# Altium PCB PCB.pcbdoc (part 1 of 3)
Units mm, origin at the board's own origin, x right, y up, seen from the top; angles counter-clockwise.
Board outline 65.2 x 64.45 mm, 2 copper layers (Top Layer, Bottom Layer); 194 components, 135 nets, 803 pads, 401 vias.
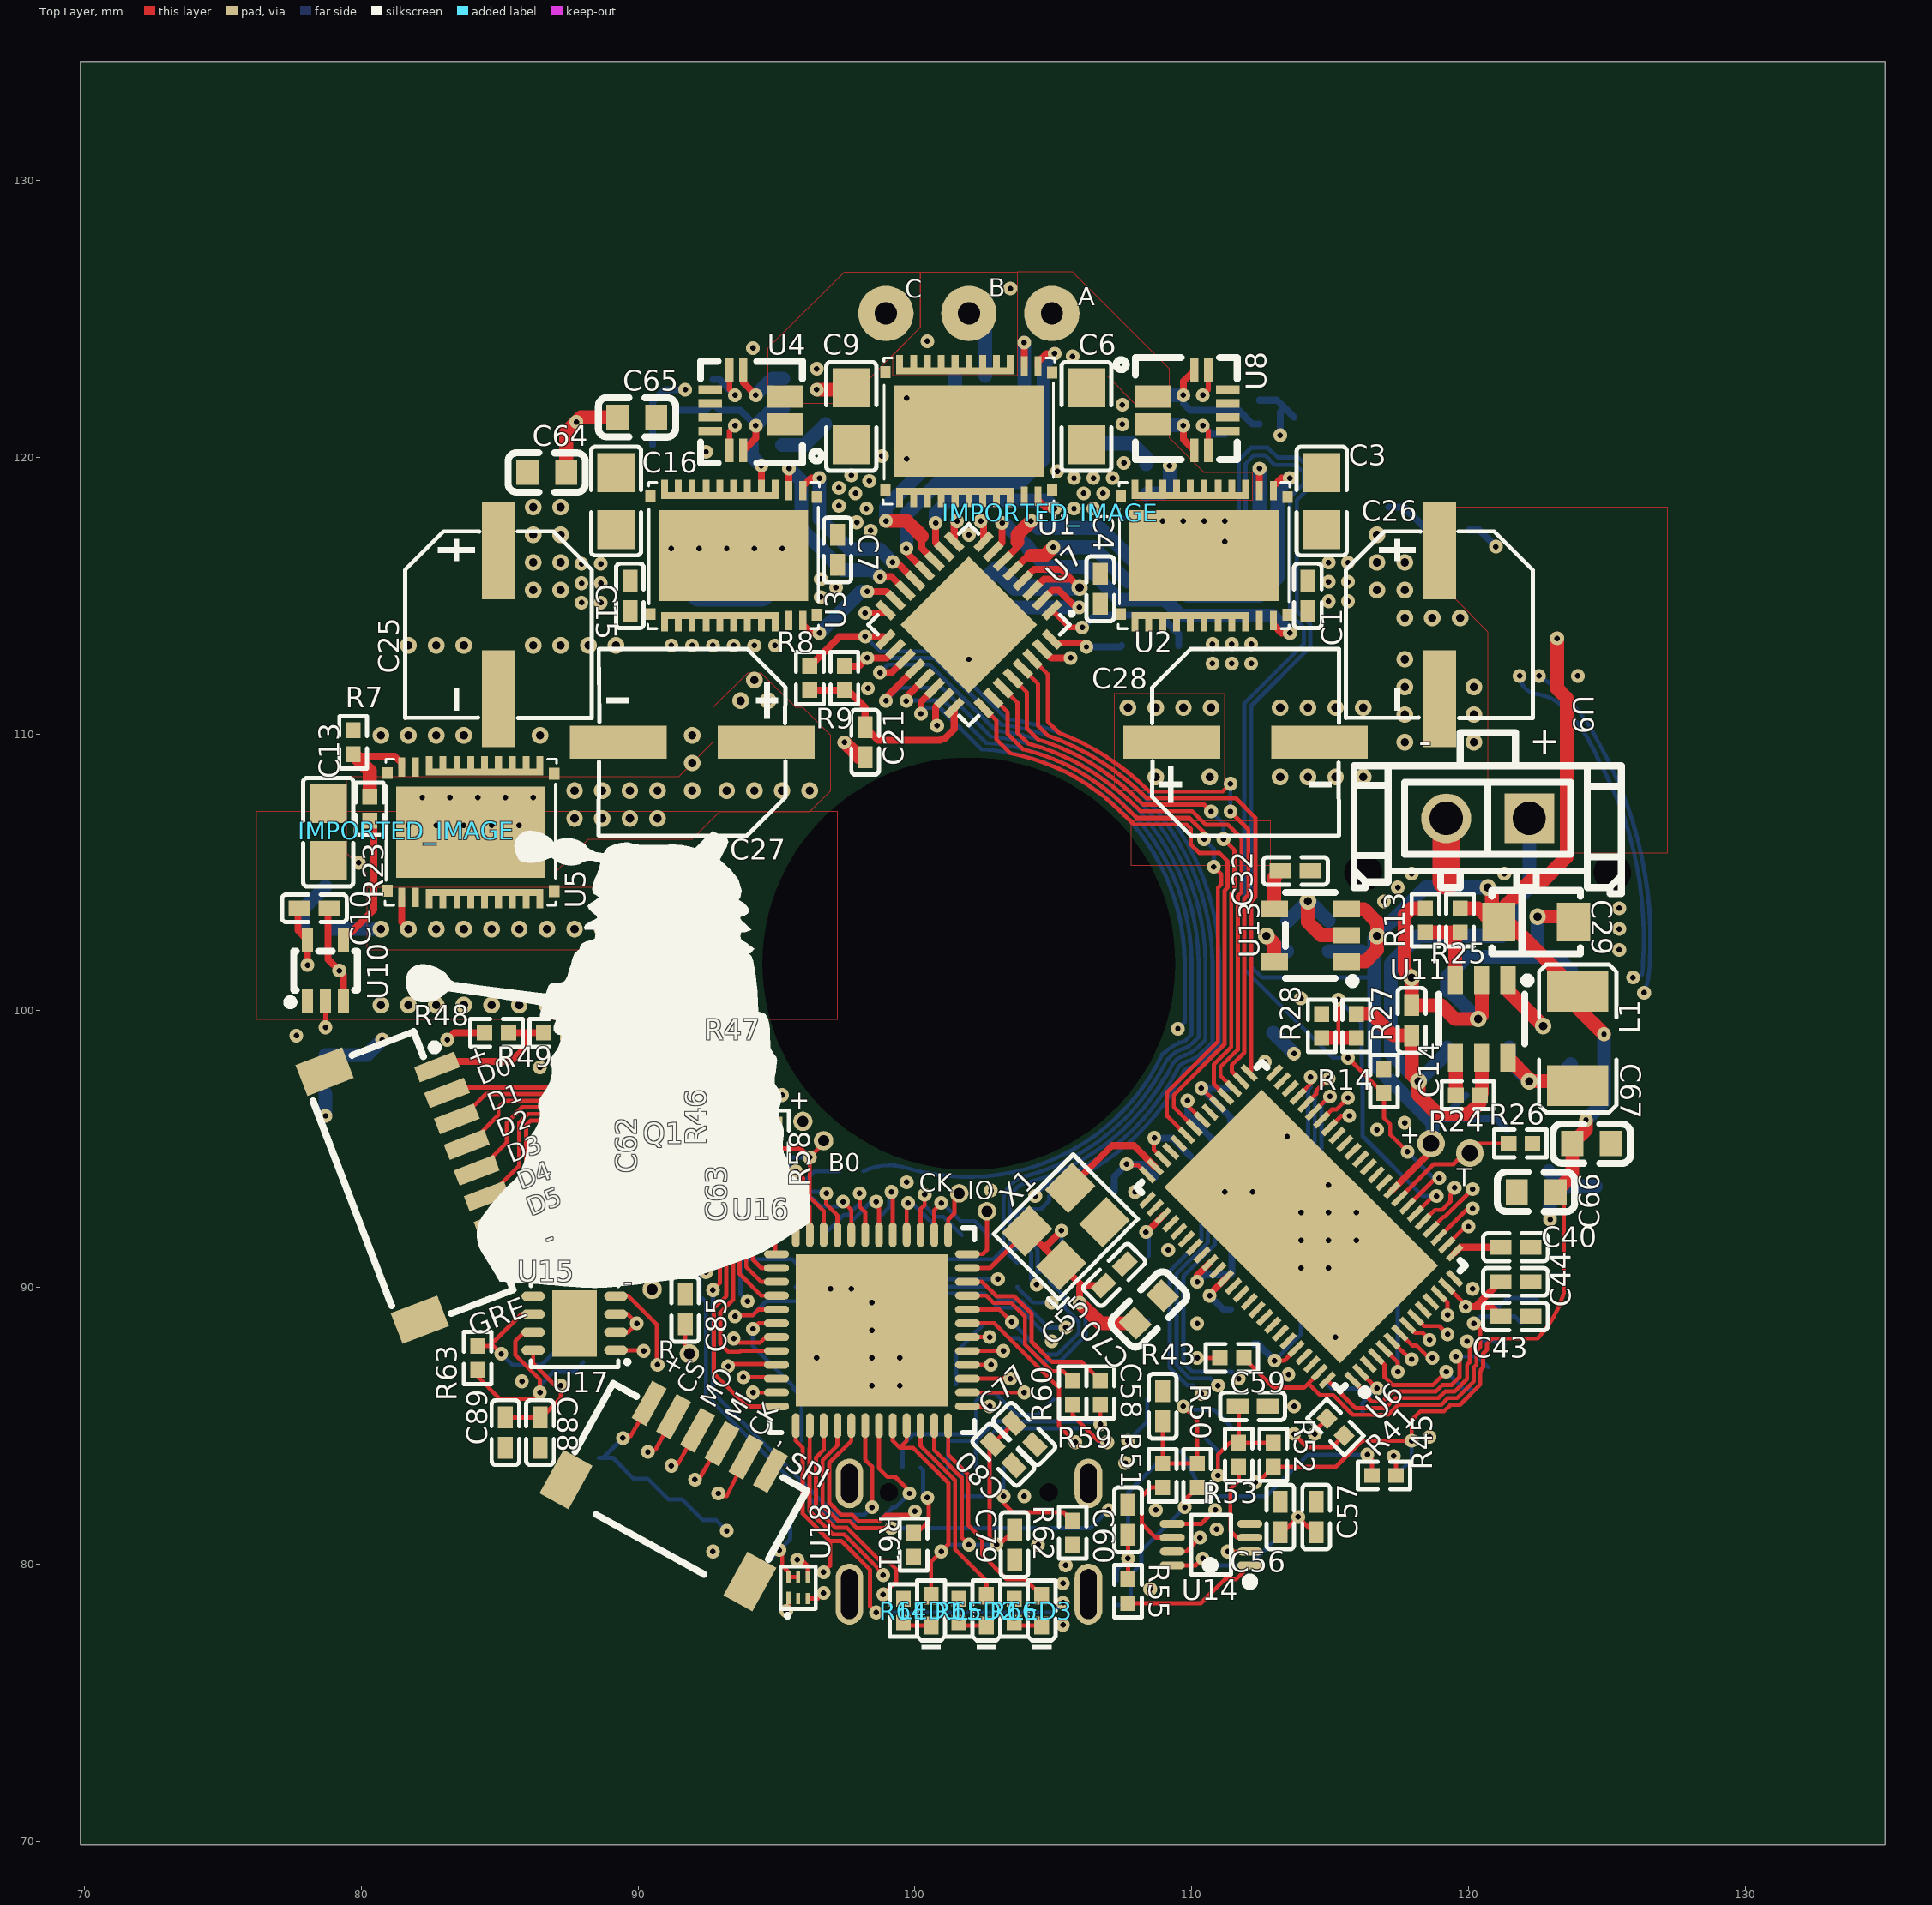
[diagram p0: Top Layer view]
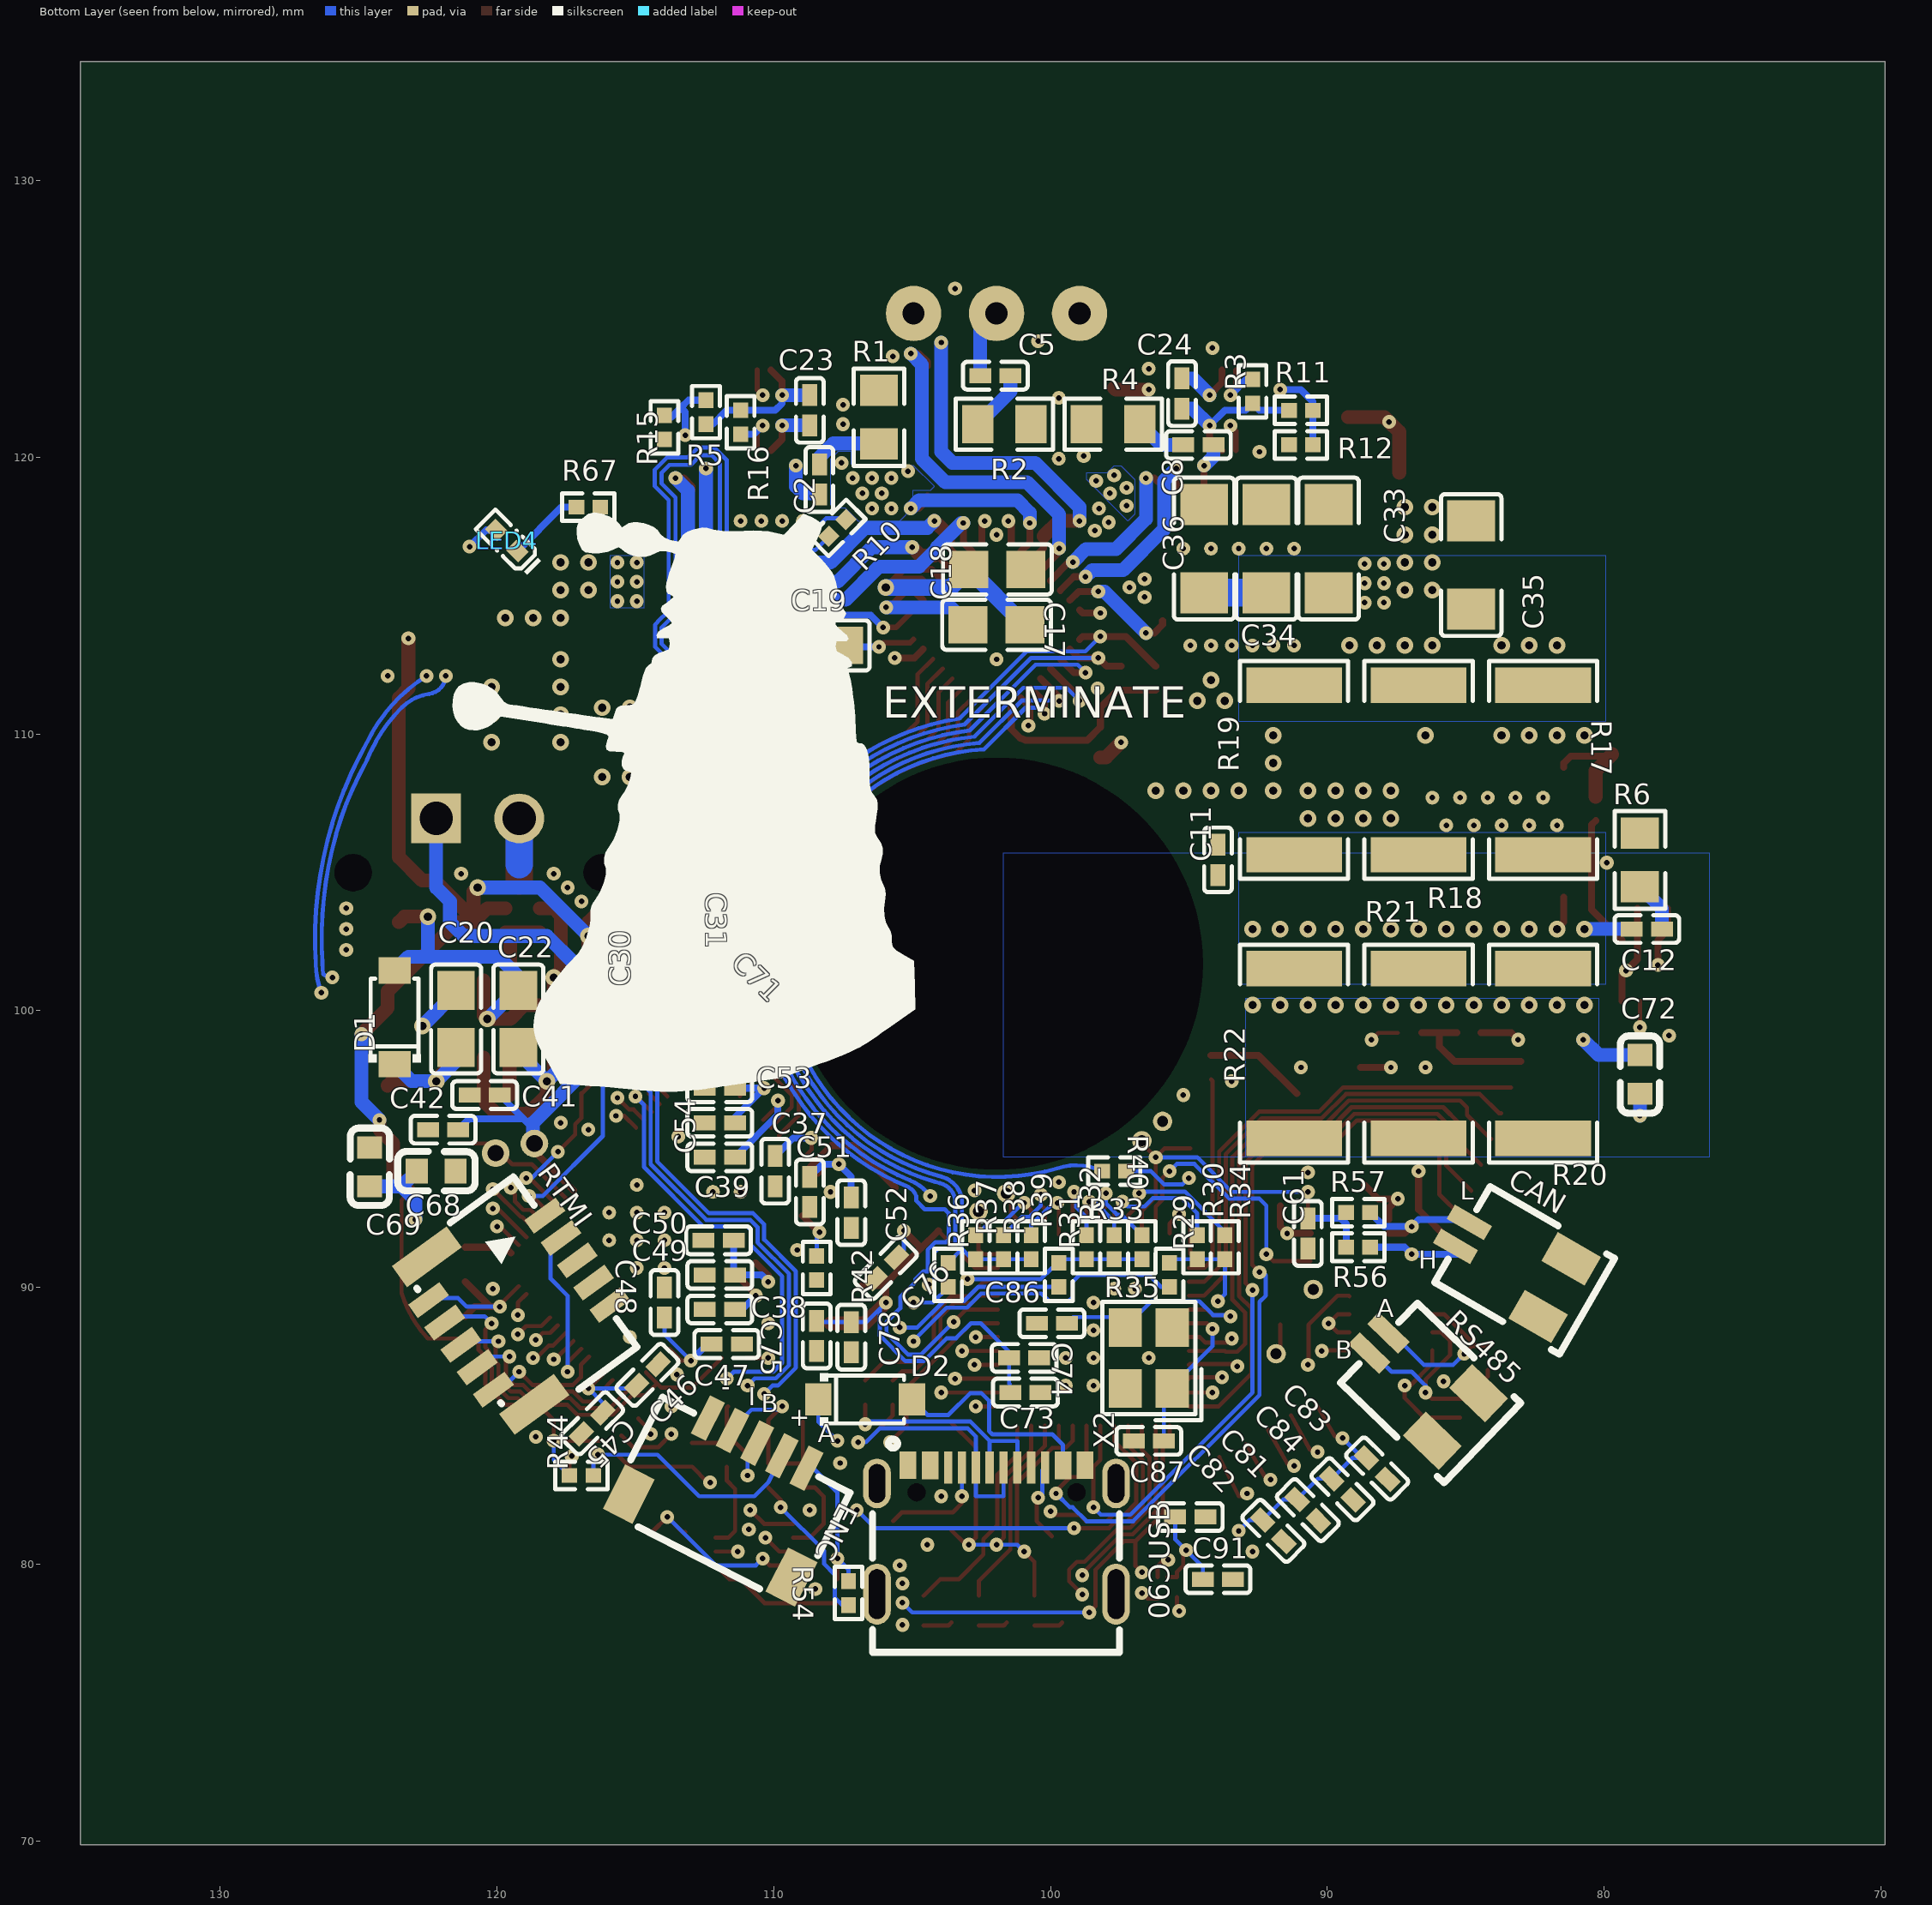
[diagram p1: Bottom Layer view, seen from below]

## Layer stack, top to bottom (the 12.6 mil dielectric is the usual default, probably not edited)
Top Solder: solder mask 0.0102, Solder Resist, Dk 3.5
Top Layer: signal copper 0.0356
Dielectric 1: dielectric 0.32, FR-4, Dk 4.8
Bottom Layer: signal copper 0.0356
Bottom Solder: solder mask 0.0102, Solder Resist, Dk 3.5

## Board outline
135.05,69.85 69.85,69.85 69.85,134.3 135.05,134.3
cut-out: 109.4,101.7 ccw(c101.95,101.7) 94.5,101.7 ccw(c101.95,101.7)
cut-out: 105.165,82.593 ccw(c104.84,82.593) 104.515,82.593 ccw(c104.84,82.593)
cut-out: 99.385,82.593 ccw(c99.06,82.593) 98.735,82.593 ccw(c99.06,82.593)

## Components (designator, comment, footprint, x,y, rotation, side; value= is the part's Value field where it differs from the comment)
C1 "CC0402KRX7R0BB103" C0402 114.2,114.995 r270 top
C2 "GRM155R72A472KA01D" C0402 108.35,119.2 r270 bottom
C3 "CL21B104KCFNNNE" C0805 114.7,118.42 r90 top
C4 "CC0402KRX7R0BB103" C0402 106.7,115.245 r270 top
C5 "GRM155R72A472KA01D" C0402 101.995,122.95 r0 bottom
C6 "CL21B104KCFNNNE" C0805 106.2,121.48 r90 top
C7 "CC0402KRX7R0BB103" C0402 97.2,116.655 r270 top
C8 "GRM155R72A472KA01D" C0402 94.655,120.45 r180 bottom
C9 "CL21B104KCFNNNE" C0805 97.7,121.48 r90 top
C10 "CC0402KRX7R7BB104" C0402 78.3,103.7 r0 top
C11 "CC0402KRX7R0BB103" C0402 93.95,105.45 r90 bottom
C12 "GRM155R72A472KA01D" C0402 78.45,102.95 r0 bottom
C13 "CL21B104KCFNNNE" C0805 78.8,106.45 r90 top
C14 "CC0402KRX7R0BB103" C0402 117.95,99.655 r90 top
C15 "CC0402KRX7R0BB103" C0402 89.7,114.995 r270 top
C16 "CL21B104KCFNNNE" C0805 89.2,118.42 r90 top
C17 "C0805X105K101T" C0805 101.95,113.95 r0 bottom
C18 "CL21B104KCFNNNE" C0805 101.92,115.95 r0 bottom
C19 "C2012X7R2A473KT0L0U" C0805 108.5,113.2 r0 bottom
C20 "CL21B104KCFNNNE" C0805 119.23,99.7 r90 bottom
C21 "CL05A105KA5NQNC" C0402 98.2,109.7 r90 top
C22 "CL21B104KCFNNNE" C0805 121.48,99.7 r270 bottom
C23 "CC0402KRX7R7BB104" C0402 108.7,121.7 r90 bottom
C24 "CC0402KRX7R7BB104" C0402 95.25,122.305 r270 bottom
C25 "VKMC1201J680MV" CAP-SMD_BD6.3-L6.6-W6.6-LS7.6-FD 84.95,113.95 r270 top
C26 "VKMC1201J680MV" CAP-SMD_BD6.3-L6.6-W6.6-LS7.6-FD 118.95,113.95 r270 top
C27 "VKMC1201J680MV" CAP-SMD_BD6.3-L6.6-W6.6-LS7.6-FD 91.95,109.7 r180 top
C28 "VKMC1201J680MV" CAP-SMD_BD6.3-L6.6-W6.6-LS7.6-FD 111.95,109.7 r0 top
C29 "TLJA107M010R1400" CAP-SMD_L3.2-W1.6 122.45,103.2 r0 top
C30 "CL05A106MP5NUNC" C0402 114.95,102.7 r270 bottom
C31 "GRM155R60J226ME11D" C0402 113.45,102.7 r270 bottom
C32 "CL05B103KB5NNNC" C0402 113.75,105.05 r180 top
C33 "GRM31CC72A475KE11L" C1206 89.95,116.7 r90 bottom
C34 "GRM31CC72A475KE11L" C1206 92.2,116.7 r90 bottom
C35 "GRM31CC72A475KE11L" C1206 84.8,116.107 r90 bottom
C36 "GRM31CC72A475KE11L" C1206 94.45,116.7 r90 bottom
C37 "CC0402KRX7R7BB104" C0402 109.95,94.2 r90 bottom
C38 "CC0402KRX7R7BB104" C0402 111.95,89.2 r180 bottom
C39 "CC0402KRX7R7BB104" C0402 111.95,94.7 r0 bottom
C40 "CC0402KRX7R7BB104" C0402 121.7,91.45 r0 top
C41 "CC0402KRX7R7BB104" C0402 120.45,96.95 r0 bottom
C42 "CL05A106MP5NUNC" C0402 121.95,95.7 r180 bottom
C43 "CC0402KRX7R7BB104" C0402 121.7,88.95 r0 top
C44 "CL05A106MP5NUNC" C0402 121.7,90.2 r180 top
C45 "CC0402KRX7R7BB104" C0402 116.565,85.085 r315 bottom
C46 "CL05A106MP5NUNC" C0402 114.565,86.835 r315 bottom
C47 "CC0402KRX7R7BB104" C0402 111.7,87.95 r180 bottom
C48 "CL05A106MP5NUNC" C0402 113.95,89.45 r270 bottom
C49 "CC0402KRX7R7BB104" C0402 111.95,90.45 r0 bottom
C50 "CL05A106MP5NUNC" C0402 111.995,91.7 r180 bottom
C51 "CC0402KRX7R7BB104" C0402 108.7,93.45 r270 bottom
C52 "CL05A106MP5NUNC" C0402 107.2,92.7 r90 bottom
C53 "CC0402KRX7R7BB104" C0402 111.95,97.2 r0 bottom
C54 "CL05A106MP5NUNC" C0402 111.95,95.95 r180 bottom
C55 "CC0402KRX7R7BB104" C0402 107.2,90.45 r225 top
C56 "CC0402KRX7R7BB104" C0402 113.2,81.7 r90 top
C57 "CL05A106MP5NUNC" C0402 114.5,81.7 r270 top
C58 "CC0402JRNPO9BN101" C0402 108.95,85.7 r270 top
C59 "CC0402JRNPO9BN101" C0402 112.2,85.7 r180 top
C60 "CC0402JRNPO9BN101" C0402 107.7,81.595 r270 top
C61 "0402B472K500CT" C0402 90.7,91.95 r270 bottom
C62 "CC0402KRX7R7BB104" C0402 89.2,93.7 r0 top
C63 "CC0402KRX7R7BB104" C0402 91.7,93.495 r90 top
C64 "CL10A226MP8NUNE" C0603 86.7,119.45 r0 top
C65 "CL10A226MP8NUNE" C0603 89.95,121.45 r180 top
C66 "CL10A226MP8NUNE" C0603 122.45,93.45 r0 top
C67 "CL10A226MP8NUNE" C0603 124.45,95.2 r180 top
C68 "CL10A226MP8NUNE" C0603 122.2,94.2 r0 bottom
C69 "CL10A226MP8NUNE" C0603 124.6,94.35 r270 bottom
C70 "CL10A226MP8NUNE" C0603 108.45,89.2 r225 top
C71 "CL10A226MP8NUNE" C0603 112.45,99.7 r315 bottom
C72 "CL10A226MP8NUNE" C0603 78.7,97.7 r90 bottom
C73 "CC0402KRX7R7BB104" C0402 100.905,86.2 r180 bottom
C74 "CL05A106MP5NUNC" C0402 100.95,87.45 r0 bottom
C75 "CC0402KRX7R7BB104" C0402 108.45,88.245 r270 bottom
C76 "CL05A106MP5NUNC" C0402 105.95,90.7 r135 bottom
C77 "CC0402KRX7R7BB104" C0402 103.95,84.7 r315 top
C78 "CL05A106MP5NUNC" C0402 107.2,88.2 r90 bottom
C79 "CC0402KRX7R7BB104" C0402 103.6,80.7 r270 top
C80 "CL05A106MP5NUNC" C0402 103.2,83.95 r135 top
C81 "CC0402KRX7R7BB104" C0402 90.7,81.95 r225 bottom
C82 "CL05A106MP5NUNC" C0402 91.95,81.2 r45 bottom
C83 "CC0402KRX7R7BB104" C0402 88.2,83.45 r225 bottom
C84 "CL05A106MP5NUNC" C0402 89.45,82.7 r45 bottom
C85 "CC0402KRX7R7BB104" C0402 91.7,89.2 r90 top
C86 "0402CG150J500NT" C0402 99.95,88.7 r180 bottom
C87 "0402CG150J500NT" C0402 96.45,84.45 r180 bottom
C88 "CC0402KRX7R7BB104" C0402 86.45,84.75 r270 top
C89 "CL05A106MP5NUNC" C0402 85.2,84.75 r90 top
C90 "CC0402KRX7R7BB104" C0402 93.95,79.45 r180 bottom
C91 "CL05A106MP5NUNC" C0402 94.95,81.7 r0 bottom
CAN "A1002WR-S-2P" CONN-SMD_A1002WR-S-2P 83.45,90.95 r120 bottom
D1 "DSK16" SOD-123_L2.8-W1.8-LS3.7-RD 123.7,99.758 r90 bottom
D2 "DSK16" SOD-123_L2.8-W1.8-LS3.7-RD 106.7,85.95 r180 bottom
ENC "A1002WR-S-5P" CONN-SMD_A1002WR-S-5P 111.45,82.7 r207 bottom
GRE "A1002WR-S-8P" CONN-SMD_A1002WR-S-8P 82.19,94.005 r291 top
IMPORTED_IMAGE "IMPORTED_IMAGE" IMPORTED_IMAGE 81.613,106.513 r0 top
IMPORTED_IMAGE "IMPORTED_IMAGE" IMPORTED_IMAGE 104.894,118.001 r0 top
L1 "CBC3225T220KR" L1210 123.95,98.997 r90 top
LED1 "MHT136UBCT" LED0402-RD_BLUE 100.584,78.316 r90 top
LED2 "MHT136UBCT" LED0402-RD_BLUE 102.584,78.316 r90 top
LED3 "MHT136UBCT" LED0402-RD_BLUE 104.584,78.316 r90 top
LED4 "MHT136CSCT" LED0402-RD_ORANGE 119.646,116.992 r45 bottom
Q1 "AP2302B" SOT-23_L2.9-W1.3-P1.90-LS2.4-BR 89.95,97.95 r0 top
R1 "0805W8F220KT5E" R0805 106.2,121.45 r270 bottom
R2 "0805W8F220KT5E" R0805 101.666,121.2 r0 bottom
R3 "0402WGF1002TCE" R0402 92.7,122.383 r270 bottom
R4 "0805W8F220KT5E" R0805 97.734,121.2 r180 bottom
R5 "0402WGF1002TCE" R0402 111.2,121.267 r90 bottom
R6 "0805W8F220KT5E" R0805 78.7,105.45 r270 bottom
R7 "0402WGF1002TCE" R0402 79.7,109.7 r270 top
R8 "0402WGF1002TCE" R0402 96.2,112.017 r270 top
R9 "0402WGF1002TCE" R0402 97.45,112.017 r270 top
R10 "NCP15XH103F03RC" R0402 107.7,117.45 r135 bottom
R11 "AR02BTC2001" R0402 90.95,121.7 r0 bottom
R12 "AR02BTC2001" R0402 90.95,120.45 r180 bottom
R13 "0402WGF1002TCE" R0402 118.45,103.267 r270 top
R14 "0402WGF1002TCE" R0402 116.95,97.45 r270 top
R15 "AR02BTC2001" R0402 113.95,121.083 r90 bottom
R16 "AR02BTC2001" R0402 112.45,121.633 r270 bottom
R17 "RC2512JK-7W6R8L" R2512 82.2,108.7 r90 bottom
R18 "RC2512JK-7W6R8L" R2512 86.7,108.7 r270 bottom
R19 "RC2512JK-7W6R8L" R2512 91.2,108.7 r270 bottom
R20 "RC2512JK-7W6R8L" R2512 82.2,98.45 r90 bottom
R21 "RC2512JK-7W6R8L" R2512 86.7,98.45 r90 bottom
R22 "RC2512JK-7W6R8L" R2512 91.2,98.45 r90 bottom
R23 "0402WGJ0561TCE" R0402 80.3,107.3 r90 top
R24 "PTFR0402B100KN9" R0402 119.98,96.95 r0 top
R25 "RTT025492FTH" R0402 119.7,103.267 r90 top
R26 "0402WGF1002TCE" R0402 121.883,95.2 r180 top
R27 "PTFR0402B100KN9" R0402 115.95,99.45 r90 top
R28 "0402WGF1002TCE" R0402 114.7,99.45 r270 top
R29 "RC0402FR-070RL" R0402 95.7,90.45 r270 bottom
R30 "RC0402FR-070RL" R0402 94.7,91.45 r90 bottom
R31 "RC0402FR-070RL" R0402 99.7,90.45 r270 bottom
R32 "RC0402FR-070RL" R0402 98.7,91.45 r90 bottom
R33 "RC0402FR-0718KL" R0402 97.7,91.45 r90 bottom
R34 "0402WGF4532TCE" R0402 93.7,91.45 r90 bottom
R35 "0402WGF7502TCE" R0402 96.7,91.45 r90 bottom
R36 "RC0402FR-070RL" R0402 103.7,90.45 r270 bottom
R37 "RC0402FR-070RL" R0402 102.7,91.45 r90 bottom
R38 "RC0402FR-0718KL" R0402 101.7,91.45 r90 bottom
R39 "0402WGF7502TCE" R0402 100.7,91.45 r90 bottom
R40 "RC0402FR-070RL" R0402 97.7,94.2 r180 bottom
R41 "0402WGF1002TCE" R0402 115.2,84.95 r135 top
R42 "0402WGF1002TCE" R0402 108.45,90.7 r90 bottom
R43 "0402WGF1002TCE" R0402 111.45,87.45 r180 top
R44 "RC0402FR-070RL" R0402 116.95,83.2 r0 bottom
R45 "RC0402FR-070RL" R0402 116.95,83.2 r0 top
R46 "AC0402FR-0710KL" R0402 92.7,97.95 r90 top
R47 "0402WGF2200TCE" R0402 94.2,97.95 r90 top
R48 "RC0402FR-070RL" R0402 84.883,99.2 r180 top
R49 "RC0402FR-070RL" R0402 87.017,99.2 r0 top
R50 "0402WGF1002TCE" R0402 110.2,83.2 r270 top
R51 "AR02BTC2001" R0402 108.95,83.2 r270 top
R52 "0402WGF1002TCE" R0402 112.95,83.95 r270 top
R53 "AR02BTC2001" R0402 111.7,83.95 r90 top
R54 "0402WGF1002TCE" R0402 107.3,78.95 r270 bottom
R55 "AR02BTC2001" R0402 107.7,79.017 r90 top
R56 "0402WGF604JTCE" R0402 88.883,91.45 r0 bottom
R57 "0402WGF604JTCE" R0402 88.883,92.7 r180 bottom
R58 "PTFR0402B100KN9" R0402 94.95,95.45 r90 top
R59 "AC0402FR-0722RL" R0402 106.7,86.2 r90 top
R60 "AC0402FR-0722RL" R0402 105.7,86.2 r90 top
R61 "0402WGF5101TCE" R0402 99.95,80.7 r270 top
R62 "0402WGF5101TCE" R0402 105.7,81.133 r270 top
R63 "RC0402FR-07120RL" R0402 84.2,87.45 r270 top
R64 "AC0402FR-07470RL" R0402 99.584,78.316 r90 top
R65 "AC0402FR-07470RL" R0402 101.584,78.316 r90 top
R66 "AC0402FR-07470RL" R0402 103.584,78.316 r90 top
R67 "0402WGJ0561TCE" R0402 116.7,118.2 r180 bottom
RS485 "A1002WR-S-2P" CONN-SMD_A1002WR-S-2P 86.75,86.651 r134 bottom
RTMI "DF20F-10DP-1H(59)" CONN-SMD_DF20F-10DP-1H-59 119.2,89.45 r234 bottom
SPI "A1002WR-S-6P" CONN-SMD_A1002WR-S-6P 91.65,82.9 r331 top
U1 "CSD88599Q5DCT" SON-22_L5.0-W6.0-P0.50-CSD88599Q5DCT 101.95,120.95 r270 top
U2 "CSD88599Q5DCT" SON-22_L5.0-W6.0-P0.50-CSD88599Q5DCT 110.45,116.45 r270 top
U3 "CSD88599Q5DCT" SON-22_L5.0-W6.0-P0.50-CSD88599Q5DCT 93.45,116.45 r270 top
U4 "ACS711KEXLT-31AB-T" IC-SMD_ACS711KEXLT-15AB-T 93.95,121.7 r180 top
U5 "CSD88599Q5DCT" SON-22_L5.0-W6.0-P0.50-CSD88599Q5DCT 83.95,106.45 r90 top
U6 "TMC4671-LA" QFN-76_L10.5-W6.5-P0.40-TL-EP 113.95,92.2 r135 top
U7 "DRV8320SRTVR" WQFN-32_L5.0-W5.0-P0.50-TL-EP3.5 101.95,113.95 r225 top
U8 "ACS711KEXLT-31AB-T" IC-SMD_ACS711KEXLT-15AB-T 109.95,121.7 r0 top
U9 "436500215" CONN-TH_436500215 120.7,106.95 r0 top
U10 "SN74LVC1G17DCKR" SC-70-5_L2.1-W1.3-P0.65-LS2.1-BR 78.7,101.45 r270 top
U11 "LMR16006XDDCR" SOT-23-6_L2.9-W1.6-P0.95-LS2.8-BR 120.48,99.7 r90 top
U13 "SPX3819M5-L-3-3/TR" SOT-23-5_L3.0-W1.7-P0.95-LS2.8-BR 114.288,102.723 r0 top
U14 "SN74LVC3G17DCUR" VSSOP-8_L2.4-W2.1-P0.50-LS3.2-BL 110.7,80.7 r90 top
U15 "MCP2542FDT-H/MNY" TDFN-8_L3.0-W2.0-P0.50-TL-EP 89.2,91.7 r180 top
U16 "STM32G431CBU6" UFQFPN-48_L7.0-W7.0-P0.50-BL-EP 98.45,88.45 r270 top
U17 "MAX14841EATA+T" TDFN-8_L3.0-W3.0-P0.65-BL-EP 87.7,88.7 r90 top
U18 "SN74LVC1G10DSFR" X2SON-6_L1.0-W1.0-P0.35-TL 95.779,79.146 r90 top
USB "GT-USB-7010B" USB-SMD_GT-USB-7010B 101.95,81.2 r180 bottom
X1 "OT322525MJBA4SL" OSC-SMD_4P-L3.2-W2.5-BL 105.45,92.2 r45 top
X2 "X322524MOB4SI" CRYSTAL-SMD_4P-L3.2-W2.5-BL 96.45,87.45 r90 bottom

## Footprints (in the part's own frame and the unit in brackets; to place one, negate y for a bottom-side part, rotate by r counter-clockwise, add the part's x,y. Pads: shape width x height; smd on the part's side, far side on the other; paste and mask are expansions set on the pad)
C0402 [mm]
  rect 0.79x0.54 smd: 1(-0.545,0) 2(0.545,0)
  silkscreen extent -1.17,-0.5 1.17,0.5
C0603 [mm]
  rect 0.8x0.9 smd: 1(-0.7,0) 2(0.7,0)
  silkscreen extent -1.41,-0.71 1.39,0.72
C0805 [mm]
  rect 1.41x1.35 smd: 1(-1.03,0) 2(1.03,0)
  silkscreen extent -1.96,-0.9 1.96,0.9
C1206 [mm]
  rect 1.485x1.728 smd: 1(-1.593,0) 2(1.593,0)
  silkscreen extent -2.56,-1.09 2.56,1.09
CAP-SMD_BD6.3-L6.6-W6.6-LS7.6-FD [mm]
  rect 3.5x1.2 smd: 1(-2.67,0) 2(2.67,0)
  silkscreen extent -3.38,-3.38 3.38,3.38
CAP-SMD_L3.2-W1.6 [mm]
  rect 1.2x1.4 smd: 1(-1.35,0) 2(1.35,0)
  silkscreen extent -1.6,-1.14 1.6,1.14
CONN-SMD_A1002WR-S-2P [mm]
  rect 0.6x1.55 smd: 1(-0.498,1.924) 2(0.501,1.924)
  rect 1.2x1.8 smd: 3(1.201,-1.924) 4(-1.201,-1.924)
  silkscreen extent -2,-3.27 2,1.92
CONN-SMD_A1002WR-S-5P [mm]
  rect 0.6x1.55 smd: 1(-2,1.876) 2(-1,1.876) 3(0,1.876) 4(1,1.876) 5(2,1.876)
  rect 1.2x1.8 smd: 6(3.3,-1.876) 7(-3.3,-1.876)
  silkscreen extent -3.8,-2.78 3.8,1.8
CONN-SMD_A1002WR-S-6P [mm]
  rect 0.6x1.55 smd: 1(-2.5,1.939) 2(-1.5,1.939) 3(-0.498,1.936) 4(0.501,1.937) 5(1.502,1.937) 6(2.502,1.937)
  rect 1.2x1.8 smd: 7(3.801,-1.939) 8(-3.801,-1.937)
  silkscreen extent -4,-2.51 4,1.93
CONN-SMD_A1002WR-S-8P [mm]
  rect 0.6x1.55 smd: 1(-3.5,1.924) 2(-2.5,1.924) 3(-1.5,1.922) 4(-0.5,1.924) 5(0.5,1.924) 6(1.5,1.924) 7(2.5,1.924) 8(3.5,1.924)
  rect 1.2x1.8 smd: 9(4.8,-1.924) 10(-4.8,-1.924)
  silkscreen extent -5,-2.7 5,2.23
CONN-SMD_DF20F-10DP-1H-59 [mm]
  rect 0.6x1.4 smd: 1(-2,2.6) 2(-2,-2.6) 3(-1,2.6) 4(-1,-2.6) 5(0,2.6) 6(0,-2.6) 7(1,2.6) 8(1,-2.6) 9(2,2.6) 10(2,-2.6)
  rect 0.95x2.45 smd: 11(3.3,-1.725) 12(-3.3,-1.725)
  silkscreen extent -3.8,-2.69 3.8,2.5
CONN-TH_436500215 [mm]
  rect 1.8x1.8 hole 1.2: 1(1.5,0)
  round 1.8 hole 1.2: 2(-1.5,0)
  Multi-Layer board cut-out: -3.825,-1.96 -3.892,-1.667 -4.079,-1.432 -4.35,-1.302 -4.65,-1.302 -4.921,-1.432 -5.108,-1.667 -5.175,-1.96 -5.175,-1.96 -5.108,-2.253 -4.921,-2.488 -4.65,-2.618 -4.35,-2.618 -4.079,-2.488 -3.892,-2.253 -3.825,-1.96
  Multi-Layer board cut-out: 5.175,-1.96 5.108,-1.667 4.921,-1.432 4.65,-1.302 4.35,-1.302 4.079,-1.432 3.892,-1.667 3.825,-1.96 3.825,-1.96 3.892,-2.253 4.079,-2.488 4.35,-2.618 4.65,-2.618 4.921,-2.488 5.108,-2.253 5.175,-1.96
  silkscreen extent -4.83,-2.73 4.83,3.1
CRYSTAL-SMD_4P-L3.2-W2.5-BL [mm]
  rect 1.4x1.2 smd: 1(-1.1,-0.85) 2(1.1,-0.85) 3(1.1,0.85) 4(-1.1,0.85)
  silkscreen extent -2.26,-1.91 2.03,1.68
IC-SMD_ACS711KEXLT-15AB-T [mm]
  rect 1.27x0.8 smd: 1(-1.35,0.5) 2(-1.35,-0.5)
  rect 0.3x0.85 smd: 5(0.15,-1.45) 6(0.65,-1.45) 11(0.65,1.45) 12(0.15,1.45)
  rect 0.85x0.3 smd: 7(1.35,-0.75) 8(1.35,-0.25) 9(1.35,0.25) 10(1.35,0.75)
  silkscreen extent -2.67,-1.78 1.7,1.91
IMPORTED_IMAGE [mm]
  silkscreen extent 0,-16.53 14.59,0
L1210 [mm]
  rect 1.474x2.22 smd: 1(-1.703,0) 2(1.703,0)
  silkscreen extent -2.67,-1.4 2.67,1.4
LED0402-RD_BLUE [mm]
  rect 0.636x0.54 smd: 1(-0.538,0) 2(0.538,0)
  silkscreen extent -1.39,-0.54 1.09,0.54
LED0402-RD_ORANGE [mm]
  rect 0.636x0.54 smd: 1(-0.538,0) 2(0.538,0)
  silkscreen extent -1.39,-0.54 1.09,0.54
OSC-SMD_4P-L3.2-W2.5-BL [mm]
  rect 1.4x1.2 smd: 1(-1.1,-0.875) 2(1.1,-0.875) 3(1.1,0.875) 4(-1.1,0.875)
  silkscreen extent -2.29,-1.9 2.03,1.65
QFN-76_L10.5-W6.5-P0.40-TL-EP [mm]
  rect 0.7x0.205 smd: 1(-5.25,2.6) 2(-5.25,2.2) 3(-5.25,1.8) 4(-5.25,1.4) 5(-5.25,1) 6(-5.25,0.6) 7(-5.25,0.2) 8(-5.25,-0.2) 9(-5.25,-0.6) 10(-5.25,-1) 11(-5.25,-1.4) 12(-5.25,-1.8) 13(-5.25,-2.2) 14(-5.25,-2.6) 39(5.25,-2.6) 40(5.25,-2.2) 41(5.25,-1.8) 42(5.25,-1.4) 43(5.25,-1) 44(5.25,-0.6) 45(5.25,-0.2) 46(5.25,0.2) 47(5.25,0.6) 48(5.25,1) 49(5.25,1.4) 50(5.25,1.8) 51(5.25,2.2) 52(5.25,2.6)
  rect 0.205x0.7 smd: 15(-4.6,-3.25) 16(-4.2,-3.25) 17(-3.8,-3.25) 18(-3.4,-3.25) 19(-3,-3.25) 20(-2.6,-3.25) 21(-2.2,-3.25) 22(-1.8,-3.25) 23(-1.4,-3.25) 24(-1,-3.25) 25(-0.6,-3.25) 26(-0.2,-3.25) 27(0.2,-3.25) 28(0.6,-3.25) 29(1,-3.25) 30(1.4,-3.25) 31(1.8,-3.25) 32(2.2,-3.25) 33(2.6,-3.25) 34(3,-3.25) 35(3.4,-3.25) 36(3.8,-3.25) 37(4.2,-3.25) 38(4.6,-3.25) 53(4.6,3.25) 54(4.2,3.25) 55(3.8,3.25) 56(3.4,3.25) 57(3,3.25) 58(2.6,3.25) 59(2.2,3.25) 60(1.8,3.25) 61(1.4,3.25) 62(1,3.25) 63(0.6,3.25) 64(0.2,3.25) 65(-0.2,3.25) 66(-0.6,3.25) 67(-1,3.25) 68(-1.4,3.25) 69(-1.8,3.25) 70(-2.2,3.25) 71(-2.6,3.25) 72(-3,3.25) 73(-3.4,3.25) 74(-3.8,3.25) 75(-4.2,3.25) 76(-4.6,3.25)
  rect 9x5 smd: 77(0,0)
  silkscreen extent -5.99,-3.2 5.2,3.2
R0402 [mm]
  rect 0.566x0.54 smd: 1(-0.433,0) 2(0.433,0)
  silkscreen extent -0.94,-0.5 0.94,0.5
R0805 [mm]
  rect 1.133x1.377 smd: 1(-0.966,0) 2(0.966,0)
  silkscreen extent -1.76,-0.92 1.76,0.92
R2512 [mm]
  rect 1.283x3.456 smd: 1(-3.066,0) 2(3.066,0)
  silkscreen extent -3.94,-1.96 3.94,1.96
SC-70-5_L2.1-W1.3-P0.65-LS2.1-BR [mm]
  rect 0.9x0.4 smd: 1(1.1,-0.65) 2(1.1,0) 3(1.1,0.65) 4(-1.1,0.65) 5(-1.1,-0.65)
  silkscreen extent -0.7,-1.4 1.27,1.15
SOD-123_L2.8-W1.8-LS3.7-RD [mm]
  rect 0.95x1.15 smd: 1(-1.692,0) 2(1.692,0)
  silkscreen extent -1.63,-0.94 1.41,0.94
SON-22_L5.0-W6.0-P0.50-CSD88599Q5DCT [mm]
  rect 0.7x0.25 smd: 1(-2.35,2.5) 2(-2.35,2) 21(2.35,2) 22(2.35,2.5)
  rect 0.45x0.25 smd: 3(-2.525,1.5) 4(-2.525,1) 5(-2.525,0.5) 6(-2.525,0) 7(-2.525,-0.5) 8(-2.525,-1) 9(-2.525,-1.5) 10(-2.525,-2) 11(-2.525,-2.5) 12(2.525,-2.5) 13(2.525,-2) 14(2.525,-1.5) 15(2.525,-1) 16(2.525,-0.5) 17(2.525,0) 18(2.525,0.5) 19(2.525,1) 20(2.525,1.5)
  rect 0.25x4.25 smd: 11(-2.175,-0.5) 20(2.175,-0.5)
  rect 0.43x0.375 smd: 23(-2.115,3.013) 24(-2.135,-3.013) 25(2.115,-3.013) 26(2.135,3.013)
  rect 3.3x5.4 smd: 27(0,0)
  silkscreen extent -2.64,-3.1 2.64,3.1
SOT-23-5_L3.0-W1.7-P0.95-LS2.8-BR [mm]
  rect 1x0.6 smd: 1(1.3,-0.95) 2(1.3,0) 3(1.3,0.95) 4(-1.3,0.95) 5(-1.3,-0.95)
  silkscreen extent -0.9,-1.78 1.65,1.55
SOT-23-6_L2.9-W1.6-P0.95-LS2.8-BR [mm]
  rect 1x0.55 smd: 1(1.4,-0.95) 2(1.4,0) 3(1.4,0.95) 4(-1.4,0.95) 5(-1.4,0) 6(-1.4,-0.95)
  silkscreen extent -0.9,-1.78 1.52,1.55
SOT-23_L2.9-W1.3-P1.90-LS2.4-BR [mm]
  rect 1x0.8 smd: 1(1.15,-0.95) 2(1.15,0.95) 3(-1.15,0)
  silkscreen extent -0.7,-1.5 0.7,1.5
TDFN-8_L3.0-W2.0-P0.50-TL-EP [mm]
  rect 0.585x0.28 smd: 1(-1.418,0.75) 2(-1.418,0.25) 3(-1.418,-0.25) 4(-1.418,-0.75) 5(1.418,-0.75) 6(1.418,-0.25) 7(1.418,0.25) 8(1.418,0.75)
  rect 1.5x1.55 smd: 9(0,0)
  silkscreen extent -2.08,-1.08 1.58,1.08
TDFN-8_L3.0-W3.0-P0.65-BL-EP [mm]
  oval 0.35x0.84 smd: 1(-0.975,-1.495) 2(-0.325,-1.495) 3(0.325,-1.495) 4(0.975,-1.495) 5(0.975,1.495) 6(0.325,1.495) 7(-0.325,1.495) 8(-0.975,1.495)
  rect 2.4x1.6 smd: 9(0,0)
  silkscreen extent -1.58,-1.98 1.58,1.58
UFQFPN-48_L7.0-W7.0-P0.50-BL-EP [mm]
  oval 0.28x0.9 smd: 1(-2.751,-3.449) 2(-2.25,-3.449) 3(-1.75,-3.449) 4(-1.25,-3.449) 5(-0.749,-3.449) 6(-0.249,-3.449) 7(0.249,-3.449) 8(0.749,-3.449) 9(1.25,-3.449) 10(1.75,-3.449) 11(2.251,-3.449) 12(2.751,-3.449) 25(2.751,3.449) 26(2.251,3.449) 27(1.75,3.449) 28(1.25,3.449) 29(0.749,3.449) 30(0.249,3.449) 31(-0.249,3.449) 32(-0.749,3.449) 33(-1.25,3.449) 34(-1.75,3.449) 35(-2.25,3.449) 36(-2.751,3.449)
  oval 0.9x0.28 smd: 13(3.449,-2.751) 14(3.449,-2.251) 15(3.449,-1.75) 16(3.449,-1.25) 17(3.449,-0.749) 18(3.449,-0.249) 19(3.449,0.249) 20(3.449,0.749) 21(3.449,1.25) 22(3.449,1.75) 23(3.449,2.25) 24(3.449,2.751) 37(-3.449,2.751) 38(-3.449,2.25) 39(-3.449,1.75) 40(-3.449,1.25) 41(-3.449,0.749) 42(-3.449,0.249) 43(-3.449,-0.249) 44(-3.449,-0.749) 45(-3.449,-1.25) 46(-3.449,-1.75) 47(-3.449,-2.251) 48(-3.449,-2.751)
  rect 5.5x5.5 smd: 49(0,0)
  silkscreen extent -3.7,-4.5 3.7,3.7
USB-SMD_GT-USB-7010B [mm]
  rect 0.6x0.98 smd: 1(-3.2,2.373) 12(3.2,2.373)
  rect 0.6x1 smd: 2(-2.4,2.363) 11(2.4,2.363)
  rect 0.3x1.15 smd: 3(-1.75,2.287) 4(-1.25,2.287) 5(-0.75,2.287) 6(-0.25,2.287) 7(0.25,2.287) 8(0.75,2.287) 9(1.25,2.287) 10(1.75,2.287)
  oval 1x2.2 hole 0.6 slot 1.8 at 90 deg copper offset 0,0: 13(-4.32,-2.288) 14(4.32,-2.288)
  oval 1x1.8 hole 0.6 slot 1.4 at 90 deg copper offset 0,0: 15(-4.32,1.712)
  oval 1x1.8 hole 0.6 slot 1.4 at 90 deg: 16(4.32,1.712)
  silkscreen extent -4.48,-4.39 4.44,3.31
VSSOP-8_L2.4-W2.1-P0.50-LS3.2-BL [mm]
  oval 0.28x0.905 smd: 1(-0.75,-1.403) 2(-0.25,-1.403) 3(0.25,-1.403) 4(0.75,-1.403) 5(0.75,1.403) 6(0.25,1.403) 7(-0.25,1.403) 8(-0.75,1.403)
  silkscreen extent -1.49,-1.55 1.08,0.72
WQFN-32_L5.0-W5.0-P0.50-TL-EP3.5 [mm]
  rect 0.8x0.28 smd: 1(-2.5,1.75) 2(-2.5,1.25) 3(-2.5,0.75) 4(-2.5,0.25) 5(-2.5,-0.25) 6(-2.5,-0.75) 7(-2.5,-1.25) 8(-2.5,-1.75) 17(2.5,-1.75) 18(2.5,-1.25) 19(2.5,-0.75) 20(2.5,-0.25) 21(2.5,0.25) 22(2.5,0.75) 23(2.5,1.25) 24(2.5,1.75)
  rect 0.28x0.8 smd: 9(-1.75,-2.5) 10(-1.25,-2.5) 11(-0.75,-2.5) 12(-0.25,-2.5) 13(0.25,-2.5) 14(0.75,-2.5) 15(1.25,-2.5) 16(1.75,-2.5) 25(1.75,2.5) 26(1.25,2.5) 27(0.75,2.5) 28(0.25,2.5) 29(-0.25,2.5) 30(-0.75,2.5) 31(-1.25,2.5) 32(-1.75,2.5)
  rect 3.5x3.5 smd: 33(0,0)
  silkscreen extent -2.98,-2.58 2.58,2.58
X2SON-6_L1.0-W1.0-P0.35-TL [mm]
  rect 0.45x0.15 smd: 1(-0.362,0.35)
  rect 0.4x0.15 smd: 2(-0.387,0) 3(-0.387,-0.35) 4(0.387,-0.35) 5(0.387,0) 6(0.387,0.35)
  silkscreen extent -1.08,-0.64 0.76,0.63

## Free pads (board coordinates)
  round 0.5 hole 0.2: 1(81.7,106.7) 1(82.2,107.7) 1(82.7,106.7) 1(83.2,107.7) 1(83.7,106.7) 1(84.2,107.7) 1(84.7,106.7) 1(85.2,107.7) 1(85.7,106.7) 1(86.2,107.7) 1(91.2,116.7) 1(92.2,116.7) 1(93.2,116.7) 1(94.2,116.7) 1(95.2,116.7) 1(96.45,87.45) 1(96.95,89.95) 1(97.7,89.95) 1(98.45,86.45) 1(98.45,87.45) 1(98.45,88.45) 1(98.45,89.45) 1(99.45,86.45) 1(99.45,87.45) 1(99.7,122.15) 1(99.7,119.95) 1(101.95,112.7) 1(108.95,117.7) 1(109.7,117.7) 1(110.45,117.7) 1(111.2,93.45) 1(111.2,116.95) 1(111.2,117.7) 1(112.2,93.45) 1(113.45,95.45) 1(113.95,90.7) 1(113.95,91.7) 1(113.95,92.7) 1(114.95,90.7) 1(114.95,91.7) 1(114.95,92.7) 1(114.95,93.7) 1(115.2,88.2) 1(115.95,91.7) 1(115.95,92.7)
  round 2 hole 0.8: 1(98.95,125.2) 1(101.95,125.2) 1(104.95,125.2)
  round 0.67 hole 0.4: 1(102.6,92.75) 2(101.6,93.4)
  round 1 hole 0.6: 1(118.65,95.2) 2(120.05,94.85)
  round 0.7 hole 0.4: 3(90.504,89.926) 3(91.85,87.6) 4(96.7,95.3) 5(95.95,96)

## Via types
v1: diameter 0.5, hole 0.2, Top Layer to Bottom Layer, 297 vias
v2: diameter 0.6, hole 0.3, Top Layer to Bottom Layer, 104 vias

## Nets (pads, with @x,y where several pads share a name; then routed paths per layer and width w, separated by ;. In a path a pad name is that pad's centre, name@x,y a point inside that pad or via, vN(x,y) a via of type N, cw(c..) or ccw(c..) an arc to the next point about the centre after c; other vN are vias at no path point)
3.3V: C43.1 C45.1 C47.1 C49.1 C51.1 C53.1 C56.1 C62.1 C73.1 C75.1 C77.1 C79.1 C81.1 C83.1 C88.1 C90.1 pad.5 RTMI.2 U6.2 U6.13 U6.43 U6.52 U6.61 U6.72 U14.8 U15.5 U16.1 U16.20 U16.21 U16.23 U16.35 U16.48 U17.8 U18.5 X1.4 | length 106.6
  Top Layer w0.15: 85.2,85.29 86.405,85.29 86.45,85.245 87.2,85.995 v1(87.2,86.45) 87.004,86.45 86.205,87.249 U17.8@86.205,87.725 ; 87.45,99.2 88.15,99.2 v1(88.4,98.95) ; v1(89.45,84.55) 89.733,84.625 90.455,85.871 ; U16.1@94.951,91.201 94.951,92.251 v1(95.35,92.65) 95.699,92.301 U16.48@95.699,91.949 ; v1(95.1,80.5) 95.206,80.394 95.206,79.944 95.429,79.721 95.429,79.533 U18.5@95.779,79.533 ; U16.20@99.199,85.001 99.199,84.451 99.45,84.2 ; U16.21@99.7,85.001 99.7,84.45 99.45,84.2 ; 100.584,78.854 100.584,80.084 v1(100.95,80.45) 101.211,80.711 101.211,82.926 99.937,84.2 99.45,84.2 ; U16.23@100.7,85.001 100.7,84.112 101.689,83.124 101.689,80.961 v1(101.95,80.7) ; U16.35@101.899,90.7 102.713,90.7 X1.4@104.053,92.041 ; C77.1@103.565,85.085 102.815,84.335 102.7,84.221 102.7,80.95 v1(102.95,80.7) 103.055,80.7 C79.1@103.6,81.245 ; v1(107.65,94.45) 107.677,94.423 108.051,94.423 U6.52@108.399,94.074 ; U14.8@109.297,79.95 110.15,79.95 v1(110.4,80.2) ; v1(110.2,87.45) 111.017,87.45 ; v1(110.35,97.2) 110.364,97.2 U6.43@110.945,96.619 ; v1(113,87.35) 113.343,87.35 U6.72@113.773,87.781 ; C56.1@113.2,81.155 113.305,81.155 v1(113.85,81.7) 114.395,81.155 114.5,81.155 ; v1(114.45,84.7) 114.45,84.812 114.894,85.256 ; U6.2@116.107,86.932 116.689,86.35 v1(116.7,86.35) ; v1(117.3,83.9) 117.383,83.817 117.383,83.2 ; U6.13@119.218,90.043 119.9,89.361 v1(119.9,89.3)
  Top Layer w0.25: U15.5@87.782,92.45 87.782,92.868 v1(87.45,93.2) 88.155,93.2 C62.1@88.655,93.7 ; X1.4@104.053,92.041 104.677,91.418 ; v1(105.3,92.05) 104.677,91.427 104.677,91.418 ; v1(105.95,89.45) 105.95,89.985 106.03,90.065 ; 106.815,90.065 106.03,90.065 ; v1(110.2,90.2) 110.2,90.43 U6.61@110.662,90.892 ; v1(119.9,89.3) 120.255,89.3 ; C43.1@121.155,88.95 120.805,89.3 120.255,89.3 ; 121.155,90.2 120.255,89.3 ; 104.677,91.418 105.291,90.803 106.03,90.065
  Top Layer w0.5: v1(105.95,89.45) 106.695,88.705 107.955,88.705 ; v2(112.7,102.7) 112.988,102.412 112.988,101.773
  Bottom Layer w0.15: C83.1@88.585,83.835 C83.1@88.735,83.835 ; v1(89.45,84.55) C83.1@88.735,83.835 ; v1(93.2,81.2) 92.815,81.585 92.335,81.585 91.585,82.335 C81.1@91.085,82.335 90.335,83.085 89.835,83.085 89.085,83.835 C83.1@88.735,83.835 ; C90.1@94.495,79.45 94.495,79.895 v1(95.1,80.5) 95.495,80.895 95.495,81.7 ; v1(100.95,80.45) 101.2,80.7 v1(101.95,80.7) v1(102.95,80.7) ; 101.477,86.501 101.495,86.519 101.495,87.67 102.525,88.7 102.875,88.7 103.412,88.163 103.749,88.163 104.578,87.334 105.247,87.334 106.166,88.253 106.166,89.234 ; v1(105.3,92.05) 105.3,91.35 105.565,91.085 ; v1(105.95,89.45) 106.166,89.234 ; C75.1@108.45,88.79 108.405,88.745 107.2,88.745 106.655,88.745 106.166,89.234 ; v1(110.4,80.2) 110.65,79.95 112.1,79.95 v1(113.85,81.7) ; v1(113,87.35) 113.95,88.3 113.95,88.905 ; 114.95,86.45 115.05,86.35 v1(116.7,86.35) 116.179,85.829 C45.1@116.179,85.471 ; v1(119.9,89.3) 121.095,89.3 121.407,89.612 122.407,89.612 RTMI.2@122.479,89.54
  Bottom Layer w0.25: 107.2,93.495 107.2,94 v1(107.65,94.45) 108.245,94.45 C51.1@108.7,93.995 ; v1(110.2,90.2) 110.45,90.45 C49.1@111.405,90.45 111.45,90.495 111.45,91.7 ; 111.405,95.95 111.405,96.145 v1(110.35,97.2) C53.1@111.405,97.2 ; C47.1@112.245,87.95 112.4,87.95 v1(113,87.35)
  Bottom Layer w0.5: v2(112.7,102.7) 113.245,102.155 113.45,102.155 ; 112.945,99.205 v1(113.7,98.45) ; 122.9,94.2 123.45,93.65 ; v1(122.95,92.45) 122.95,93.15 123.45,93.65 ; 124.6,93.65 123.45,93.65
5V: C10.1 C41.1 C63.1 D2.1 LED4.2 pad.1@118.65,95.2 U6.23 U13.1 U13.3 U15.3 | length 232.6
  Top Layer w0.15: v1(109.75,82.05) 109.75,82.317 110.2,82.767 ; v1(112.3,82.95) 112.383,82.95 112.95,83.517 115.217,83.517 116.15,84.45 v1(117.95,84.45) 117.95,85.2 118.267,85.517 119.118,85.517 119.357,85.756 119.695,85.756 120.428,86.489 120.428,86.95 120.45,86.972 120.45,87.024 120.528,87.102 120.528,87.601 120.666,87.74 120.666,87.95 120.866,88.15 122.495,88.15 ; 122.5,88.15 ccw(c119.462,90.998) 123.45,89.8 123.45,93.15 123.15,93.45
  Top Layer w0.25: C10.1@77.7,103.7 77.7,102.9 78.05,102.55 v1(78.05,101.65) ; v1(83.1,98.95) 83.35,99.2 84.45,99.2 ; U15.3@90.618,91.95 v1@91.495,91.95 ; v1(91.45,91.95) 91.7,92.2 C63.1@91.7,92.95 ; 93.8,120.25 94.25,120.7 v1(94.25,121.15) ; v1(109.7,122.25) 109.7,122.75 110.1,123.15 ; U6.23@117.238,93.508 118.7,94.97 pad.1@118.7,95.2
  Top Layer w0.5: 87.4,119.45 87.4,120.918 v1(87.765,121.283) 87.932,121.45 89.25,121.45 ; U13.1@115.588,101.773 116.273,101.773 116.7,102.2 v2(116.7,102.7) 116.7,103.2 116.227,103.673 U13.3@115.588,103.673 ; 119.7,103.7 120.35,103.7 120.85,103.2 ; v2(120.7,104.45) 120.85,104.3 120.85,103.3 ; 123.15,93.45 123.75,94.05 123.75,95.2 124.25,95.7 v1(124.25,96.05) ; v1(123.202,113.458) 123.202,111.648 123.55,111.3 123.55,105.55 122.701,104.701 122.251,104.701 120.85,103.3 ; v1(124.9,99.15) 123.95,100.1 123.95,100.7 121.45,103.2 120.85,103.2 ; 120.85,103.2 120.85,103.3
  Mid-Layer 1 w0.5: v1(91.45,91.95) 90.45,91.95 83.45,98.95 v1(83.1,98.95) v1(80.75,98.95) v1(78.05,101.65) 77.8,101.65 77.7,101.75 cw(c103.86,101.191) 82.246,115.938 cw(c103.091,99.937) 94.846,124.888 95.852,123.882 95.852,123.852 ; v1(94.25,121.15) 94.95,121.85 94.95,122.95 95.852,123.852 ; v1(109.7,122.25) 109.65,122.25 108.45,123.45 ; v1(123.202,113.458) ccw(c101.635,101.349) 110.452,124.458 109.45,123.456 109.45,123.45 108.45,123.45 ; 95.852,123.852 97.298,123.852 97.95,123.2 102.45,123.2 102.7,122.95 106.45,122.95 106.95,123.45 108.45,123.45
  Mid-Layer 2 w0.15: v1(107.7,84.45) 109.75,82.4 v1(109.75,82.05) 110.225,82.525 111.875,82.525 v1(112.3,82.95)
  Bottom Layer w0.15: 107.3,78.517 107.517,78.517 107.797,78.797 107.797,79.622 108.177,80.002 108.177,80.477 v1(109.75,82.05) ; 107.394,117.756 107.438,117.8 108.1,117.8 109,116.9 109.95,116.9 110.45,116.4 111.5,116.4 111.7,116.6 111.7,119.9 112.15,120.35 112.75,120.35 113.1,120 113.85,120 114.3,119.55 114.3,118.95 113.8,118.45 113.8,114.45 114.2,114.05 114.2,114.038 114.289,113.949 114.289,113.151 112.15,111.012 112.15,101.588 112.538,101.2 116.359,101.2 116.6,100.959 ; v1(107.7,84.45) 108.392,85.142 D2.1@108.392,85.95 ; 117.383,83.2 117.95,83.767 v1(117.95,84.45)
  Bottom Layer w0.25: 91.383,121.7 92.45,121.7 92.7,121.95 92.95,121.7 93.7,121.7 v1(94.25,121.15) ; v1@109.695,122.245 109.695,121.955 109.95,121.7 111.2,121.7 111.7,121.7 112.2,121.2 112.45,121.2 ; 118.7,95.745 119.047,96.092 ; C41.1@119.905,96.95 119.047,96.092 ; 121.405,95.7 121.013,96.092 119.047,96.092
  Bottom Layer w0.254: LED4.2@120.027,117.373 120.391,117.373 v1(120.993,116.77)
  Bottom Layer w0.5: 78.7,98.4 80.2,98.4 v1(80.75,98.95) ; v1(94.25,121.15) 94.86,121.76 95.25,121.76 ; 108.7,122.245 109.695,122.245 v1(109.7,122.25) ; 114.95,102.155 116.155,102.155 ; pad.1@118.7,95.2 118.7,95.745 118.7,95.95 116.6,98.05 116.6,100.959 116.6,102.6 v2(116.7,102.7) 118.45,104.45 v2(120.7,104.45) ; v1(124.25,96.05) 124.9,96.7 v1(124.9,99.15)
$1N3502: Q1.1 | length 3.7
  Top Layer w0.25: Q1.1@91.1,97 92.483,98.383 92.7,98.383 94.2,98.383
$1N6016: CAN.1 R56.1 U15.7 | length 4.7
  Top Layer w0.25: v1(86.95,91.2) 87.2,91.45 U15.7@87.782,91.45
  Bottom Layer w0.25: CAN.1@84.814,91.268 84.883,91.2 v1(86.95,91.2) 87.2,91.45 R56.1@88.45,91.45
$1N6033: U15.6 | length 4.9
  Top Layer w0.25: v1(86.95,92.2) 87.2,91.95 U15.6@87.782,91.95
  Bottom Layer w0.25: 84.866,92.346 84.97,92.45 86.7,92.45 v1(86.95,92.2) 87.95,92.2 88.45,92.7
$1N6064: C61.1 R57.1 | length 2.6
  Bottom Layer w0.25: 89.316,91.45 89.316,92.29 R57.1@89.521,92.495 ; R57.1@89.316,92.7 R57.1@89.521,92.495 ; C61.1@90.7,92.495 R57.1@89.521,92.495
$1N27747: R59.1 USB.6 USB.8 | length 8.5
  Top Layer w0.15: v1(106.7,85.05) R59.1@106.7,85.767
  Bottom Layer w0.15: USB.8@101.2,83.488 101.2,84.45 102.2,84.45 ; USB.6@102.2,83.487 102.2,84.45 ; v1(106.7,85.05) 106.602,85.148 102.898,85.148 102.2,84.45
$1N27790: R60.1 USB.5 USB.7 | length 10.8
  Top Layer w0.15: R60.1@105.7,85.767 105.7,85.375 106.625,84.45 106.9,84.45 v1(106.95,84.4)
  Bottom Layer w0.15: USB.7@101.7,83.487 101.7,82.45 102.7,82.45 USB.5@102.7,83.487 102.7,84.612 102.997,84.909 106.166,84.909 106.675,84.4 v1(106.95,84.4)
$1N28853: R61.1 USB.10 | length 2.8
  Top Layer w0.15: R61.1@99.95,81 100.5,81.55 100.5,82.35 v1(100.45,82.4)
  Bottom Layer w0.15: USB.10@100.2,83.487 100.3,83.387 100.3,82.55 v1(100.45,82.4)
$1N28894: R62.1 USB.4 | length 4
  Top Layer w0.15: v1(103.2,82.45) 103.2,82.2 103.532,81.868 105.376,81.868 R62.1@105.685,81.559
  Bottom Layer w0.15: v1(103.2,82.45) USB.4@103.2,83.487
$1N29299: USB.11 | length 8.2
  Bottom Layer w0.15: USB.11@99.55,83.487 99.55,84.3 99.939,84.689 102.101,84.689 102.223,84.81 102.223,85.898 102.502,86.177 102.898,86.177 103.689,85.386 104.444,85.386 105.008,85.95
$1N32059: RS485.1 U17.7 | length 8.1
  Top Layer w0.15: 84.2,87.017 84.2,86.775 85.002,85.973 86.223,85.973 v1(86.45,86.2) 86.45,86.666 85.558,87.558 85.558,88.058 85.875,88.375 U17.7@86.205,88.375
  Bottom Layer w0.15: v1(86.45,86.2) 86.45,86.45 86.95,86.95 87.679,86.95 RS485.1@88.015,87.286
$1N32304: R63.1 U17.6 | length 5.8
  Top Layer w0.15: R63.1@84.2,87.883 84.633,87.883 ; v1(85.05,87.6) 84.767,87.883 84.633,87.883 ; U17.6@86.205,89.025 85.776,89.025 84.633,87.883
  Bottom Layer w0.15: v1(85.05,87.6) 85.45,87.2 86.515,87.2 87.32,88.005
$1N38198: LED3.1 R66.1 | length 1
  Top Layer w0.15: R66.1@103.584,77.883 103.69,77.777 LED3.1@104.584,77.777
$1N38253: LED2.1 R65.1 | length 1
  Top Layer w0.15: R65.1@101.584,77.883 101.69,77.777 LED2.1@102.584,77.777
$1N38308: LED1.1 R64.1 | length 1
  Top Layer w0.15: R64.1@99.584,77.883 99.69,77.777 LED1.1@100.584,77.777
$1N42270: R67.1 | length 2.8
  Bottom Layer w0.254: R67.1@117.133,118.2 117.677,118.2 119.266,116.611
$3N40755: U7.2 | length 5
  Top Layer w0.25: U7.2@104.602,114.834 104.968,115.2 105.2,115.2 105.821,114.579 v1(105.939,114.579)
  Bottom Layer w0.5: 102.98,113.95 103.609,114.579 v1(105.939,114.579)
$3N40772: U7.1 | length 5.7
  Top Layer w0.2: U7.1@104.955,114.48 105.586,113.85 v1(106.05,113.85)
  Bottom Layer w0.25: v1(106.05,113.85) 106.5,114.3 108.85,114.3 109.53,113.62 109.53,113.2
$3N40773: C19.1 U7.32 | length 2.6
  Top Layer w0.2: U7.32@104.955,113.42 105.075,113.3 106.05,113.3 v1(106.2,113.15)
  Bottom Layer w0.25: v1(106.2,113.15) 107.42,113.15 C19.1@107.47,113.2
$3N50474: C2.1 | length 2.6
  Bottom Layer w0.5: 106.2,120.484 106.216,120.5 107.85,120.5 108.35,120 C2.1@108.35,119.745
$3N52263: C5.1 | length 2.2
  Bottom Layer w0.5: C5.1@101.45,122.95 101.45,122.382 102.632,121.2
$3N53370: C8.1 | length 1.9
  Bottom Layer w0.5: C8.1@95.2,120.45 96.018,120.45 96.768,121.2
$3N68599: U2.3 U2.4 U2.5 U2.6 U2.7 U2.8 U2.9 U2.10 U2.11 U8.2 | length 1.7
  Bottom Layer w0.5: 108.35,118.655 108.395,118.7 108.95,118.7 109.2,118.95 v1(109.2,119.7)
$3N73172: U3.3 U3.4 U3.5 U3.6 U3.7 U3.8 U3.9 U3.10 U3.11 U4.1 | length 1.6
  Top Layer w0.25: U3.4@94.45,118.975 v1(94.45,119.7)
  Bottom Layer w0.5: 94.11,120.45 94.11,120.04 v1(94.45,119.7)
$4N2455: C12.1 | length 1.9
  Bottom Layer w0.5: C12.1@77.905,102.95 77.905,103.689 78.7,104.484
$4N5399: R23.1 U10.4 | length 4.8
  Top Layer w0.25: U10.4@79.35,102.55 80.45,103.65 80.45,106.717 R23.1@80.3,106.867
$5N570: R24.1 U11.4 | length 1.4
  Top Layer w0.5: U11.4@119.53,98.3 119.547,98.283 R24.1@119.547,96.95
$5N859: D1.1 L1.1 U11.6 | length 6.3
  Top Layer w0.5: U11.6@121.43,98.3 122.2,97.529 v2(122.2,97.45) 123.794,97.45 L1.1@123.95,97.294
  Bottom Layer w0.5: 121.48,98.67 121.48,98.17 v2(122.2,97.45) 123.085,97.45 D1.1@123.7,98.065
$5N869: C22.1 U11.1 | length 4
  Top Layer w0.5: U11.1@121.43,101.1 121.43,100.72 v2(122.7,99.45)
  Bottom Layer w0.5: C22.1@121.48,100.73 121.48,100.67 v2(122.7,99.45)
$5N1339: R25.1 | length 3.1
  Top Layer w0.5: 118.45,102.834 R25.1@119.7,102.834 119.53,102.664 119.53,101.1
$5N3831: U13.4 | length 1.5
  Top Layer w0.5: U13.4@112.988,103.673 112.988,104.833 113.205,105.05
$6N7492: U6.50 | length 2.5
  Top Layer w0.15: v1(108.65,95.4) 108.627,95.377 108.627,94.977 U6.50@108.965,94.639
  Bottom Layer w0.25: v1(108.65,95.4) 109.295,95.4 109.95,94.745
$6N8440: U6.63 | length 1.8
  Top Layer w0.25: v1(110.65,89.7) 110.65,89.748 U6.63@111.228,90.326
  Bottom Layer w0.25: v1(110.65,89.7) 111.15,89.2 111.405,89.2
$6N8522: C39.1 U6.45 | length 3.6
  Top Layer w0.15: v1(109.85,96.75) 109.85,96.583 U6.45@110.379,96.054
  Bottom Layer w0.25: v1(109.85,96.75) 109.85,96.255 C39.1@111.405,94.7
$6N8546: C40.1 U6.15 | length 1.7
  Top Layer w0.25: U6.15@119.501,91.245 119.705,91.45 C40.1@121.155,91.45
$6N18292: ENC.4 R44.1 R45.1 | length 9.9
  Top Layer w0.15: v1(116.35,83.95) 116.517,83.783 R45.1@116.517,83.2
  Bottom Layer w0.15: ENC.4@109.628,84.073 110.2,82.95 110.7,82.45 112.7,82.45 114.2,83.95 v1(116.35,83.95) 116.517,83.783 R44.1@116.517,83.2
$6N38230: U14.6 | length 3.2
  Top Layer w0.15: 108.95,82.767 108.517,82.767 108.2,82.45 108.2,81.45 108.7,80.95 U14.6@109.297,80.95
$6N38591: R53.1 U14.3 | length 3.2
  Top Layer w0.15: R53.1@111.7,83.517 111.7,83.017 111.4,82.717 111.4,81.2 111.65,80.95 U14.3@112.103,80.95
$6N38649: R55.1 | length 5
  Top Layer w0.15: R55.1@107.7,78.584 110.334,78.584 111.2,79.45 111.603,79.45 112.103,79.95
A: pad.1@104.95,125.2 U8.1
ADC_VM: R27.1 U6.20 | length 12.5
  Top Layer w0.15: v1(115.3,100.4) 115.3,99.035 115.317,99.017 ; U6.20@118.087,92.66 118.727,93.3 v1(118.85,93.3)
  Top Layer w0.5: 114.7,99.017 115.317,99.017 R27.1@115.95,99.017
  Bottom Layer w0.15: v1(115.3,100.4) 116.129,99.571 116.156,97.594 116.177,97.573 116.177,95.473 118.35,93.3 v1(118.85,93.3)
AGPI_A: R10.1 U6.21 | length 42
  Top Layer w0.15: v1(115.65,98.3) 116.933,97.017 116.95,97.017 116.95,96.125 117.177,95.898 117.177,95.523 v1(117.8,94.9) ; U6.21@117.804,92.942 118.811,93.95 v1(118.95,93.95)
  Bottom Layer w0.15: R10.1@108.006,117.144 108.5,116.65 109.85,116.65 110.35,116.15 111.65,116.15 111.95,116.45 111.95,119.775 112.252,120.077 112.648,120.077 112.998,119.727 113.773,119.727 114.05,119.45 114.05,119.05 113.55,118.55 113.55,114.35 114.05,113.85 114.05,113.25 111.9,111.1 111.9,102.75 111.911,102.739 111.911,101.489 115.1,98.3 v1(115.65,98.3) ; v1(117.8,94.9) 118.75,93.95 v1(118.95,93.95)
AGPI_B: pad.2@120.05,94.85 U6.22 | length 4.7
  Top Layer w0.15: U6.22@117.521,93.225 118.746,94.45 119.45,94.45 120.2,95.2 121.45,95.2
B: pad.1@101.95,125.2 U1.3 U1.4 U1.5 U1.6 U1.7 U1.8 U1.9 U1.10 U1.11 | length 2.5
  Bottom Layer w0.5: pad.1@101.95,125.2 102.54,124.61 102.54,122.95
BR: R17.1 U5.3 U5.4 U5.5 U5.6 U5.7 U5.8 U5.9 U5.10 U5.11 | length 1.7
  Bottom Layer w0.5: 78.995,102.95 v2(80.7,102.95)
  other v2: 82.7,102.95 83.7,102.95 84.7,102.95 85.7,102.95 86.7,102.95 87.7,102.95 88.7,102.95 89.7,102.95 90.7,102.95 91.7,102.95 92.7,102.95
BRAKE: U6.31 U10.2 | length 52.5
  Top Layer w0.15: v1(78.7,99.4) U10.2@78.7,100.35 ; U6.31@114.975,95.771 115.404,96.2 v1(115.7,96.2)
  Mid-Layer 2 w0.15: v1(78.7,99.4) 78.75,99.45 93.95,99.45 94.35,99.85 cw(c101.952,101.668) 109.5,103.7 116.175,97.025 116.175,96.675 v1(115.7,96.2)
C: pad.1@98.95,125.2 U4.2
